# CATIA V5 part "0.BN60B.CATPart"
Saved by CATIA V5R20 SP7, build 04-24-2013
Part number: 0.BN60B
Material "Nessuno"
Bounding box of the stored display mesh (mm): x 0 to 149.213, y -124.685 to 0, z -56.919 to 41.584
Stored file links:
  C:\Users\designer2\Desktop\Ottobre 2022\25-10-2022\04\Yori Evo 48V\0.BN60B.CATPart
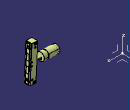
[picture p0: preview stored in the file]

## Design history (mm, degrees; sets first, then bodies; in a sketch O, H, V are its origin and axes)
AxisSystem1: origin (0, 0, 0), X (1, 0, 0), Y (0, 1, 0), Z (0, 0, 1)
Set1
  DatumSurface1
Body1 (main body), material "Nessuno"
